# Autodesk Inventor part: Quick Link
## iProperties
Company: Digiplan
Length: 1
Title: Quick Link
Author: QBZ
Shininess: 60.0
PropertySet Name: _Private Model Information
Created: 2001-02
Part Number: Quick Link
Description: 3/16 Quick Link
Document SubType Name: Modeling
Designer: QBZ
Material: Steel, Mild
Control State: 0
Master: False
Checked Out: False
PropertySet Name: Design Tracking Control
Density: 0.0
Volumn: 0.0
Area: 0.0
PropertySet Name: Model Information
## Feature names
1. Sweep1
2. Revolution2
